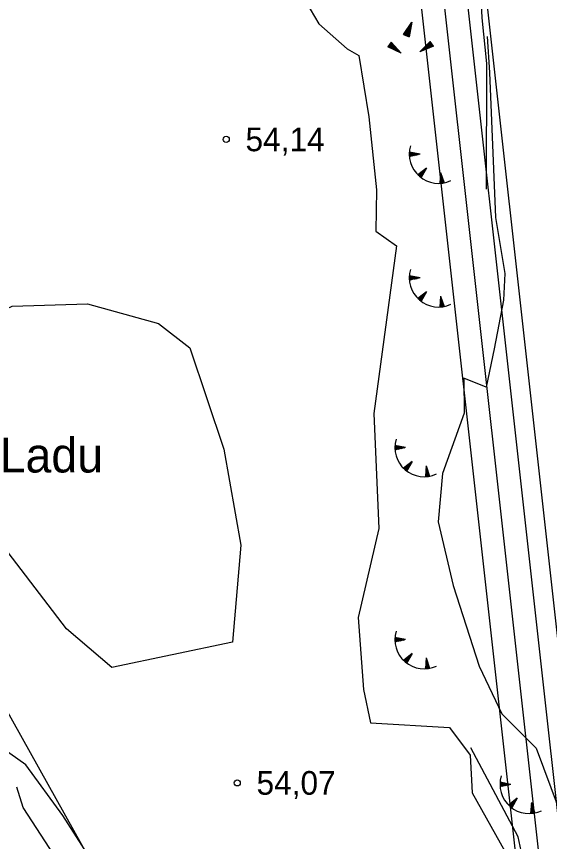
# Model space of a CAD drawing. Extents: x 532503 to 539665, y 6557663 to 6561526.
# Drawn here: x 535432.3 to 535487.5, y 6559649.2 to 6559734.6 of the extents above; entities that cross this region are included whole.
import ezdxf

# ---------------------------------------------------------------- set-up
doc = ezdxf.new("R2010")
doc.units = 0
for name, color, linetype in [('Default', 7, 'Continuous'), ('HALJASTUS', 7, 'Continuous'), ('illumineerimisjooned', 7, 'Continuous'), ('KORGUS-EH2000', 7, 'Continuous'), ('Lõige', 7, 'Continuous'), ('ME_aktiivne', 7, 'Continuous'), ('Plokid', 7, 'Continuous'), ('RELJEEF', 7, 'Continuous')]:
    doc.layers.add(name, color=color, linetype=linetype)

# ---------------------------------------------------------------- blocks, each defined once
blk = doc.blocks.new('POINT_DISPLAY')
at = {"layer": 'Default'}
blk.add_line((0, 0), (0, 0), dxfattribs=at)

msp = doc.modelspace()

# ---------------------------------------------------------------- linework, layer by layer
at = {"layer": 'illumineerimisjooned'}
msp.add_lwpolyline([(535476.016, 6559817.954), (535471.557, 6559803.013), (535503.755, 6559513.648), (535136.963, 6559567.806)], dxfattribs=at)
at = {"layer": 'KORGUS-EH2000'}
for centre in [(535454.026, 6559721.923), (535455.168, 6559655.294)]:
    msp.add_circle(centre, 0.32, dxfattribs=at)
at = {"layer": 'Lõige'}
msp.add_lwpolyline([(535150.705, 6560087.504), (535159.93, 6560069.75), (535218.82, 6559968.7), (535305.655, 6559887.851), (535461.67, 6559608.38), (535506.03, 6559511.29), (535514.367, 6559493.043)], dxfattribs=at)
at = {"layer": 'ME_aktiivne'}
msp.add_lwpolyline([(535181.4, 6559689.09), (535250.12, 6559650.95), (535250.5, 6559651.24), (535480.86, 6559827.19), (535473.59, 6559802.83), (535506.03, 6559511.29), (535131.71, 6559566.56)], close=True, dxfattribs=at)
at = {"layer": 'Plokid'}
for points in [[(535471.605, 6559811.564), (535469.118, 6559803.232), (535501.026, 6559516.477), (535140.335, 6559569.734)], [(535468.361, 6559809.086), (535466.679, 6559803.451), (535498.296, 6559519.306), (535141.263, 6559572.023)]]:
    msp.add_lwpolyline(points, dxfattribs=at)
at = {"layer": 'RELJEEF'}
for p, q in [((535472.407, 6559732.787), (535473.247, 6559734.067)), ((535472.607, 6559733.087), (535473.107, 6559733.297)), ((535472.707, 6559733.237), (535472.957, 6559733.347)), ((535472.807, 6559733.387), (535473.147, 6559733.537)), ((535472.907, 6559733.537), (535473.167, 6559733.657)), ((535472.957, 6559733.347), (535473.127, 6559733.417)), ((535473.247, 6559734.067), (535472.967, 6559732.557)), ((535472.997, 6559733.687), (535473.197, 6559733.767)), ((535473.097, 6559733.837), (535473.217, 6559733.887)), ((535473.197, 6559733.987), (535473.237, 6559734.007)), ((535472.407, 6559732.787), (535473.057, 6559733.067)), ((535472.407, 6559732.787), (535472.967, 6559732.557)), ((535472.507, 6559732.937), (535473.077, 6559733.177)), ((535472.537, 6559732.737), (535473.037, 6559732.947)), ((535472.667, 6559732.677), (535473.017, 6559732.827)), ((535472.807, 6559732.627), (535472.997, 6559732.707)), ((535472.937, 6559732.577), (535472.967, 6559732.587)), ((535471.125, 6559731.985), (535470.755, 6559731.505)), ((535470.775, 6559731.535), (535470.785, 6559731.495)), ((535470.865, 6559731.645), (535470.895, 6559731.445)), ((535470.955, 6559731.765), (535471.005, 6559731.395)), ((535471.035, 6559731.875), (535471.105, 6559731.335)), ((535471.125, 6559731.985), (535472.135, 6559730.845)), ((535471.125, 6559731.985), (535471.215, 6559731.285)), ((535471.245, 6559731.855), (535471.325, 6559731.235)), ((535471.365, 6559731.715), (535471.435, 6559731.185)), ((535471.485, 6559731.585), (535471.515, 6559731.305)), ((535474.083, 6559730.975), (535475.163, 6559732.065)), ((535475.503, 6559731.565), (535474.083, 6559730.975)), ((535475.333, 6559731.495), (535474.723, 6559731.615)), ((535475.503, 6559731.565), (535474.803, 6559731.695)), ((535475.423, 6559731.675), (535474.893, 6559731.785)), ((535475.343, 6559731.795), (535474.973, 6559731.865)), ((535475.263, 6559731.915), (535475.063, 6559731.955)), ((535475.183, 6559732.035), (535475.143, 6559732.035)), ((535475.503, 6559731.565), (535475.163, 6559732.065)), ((535472.135, 6559730.845), (535470.755, 6559731.505)), ((535471.515, 6559731.305), (535471.545, 6559731.125)), ((535471.595, 6559731.445), (535471.655, 6559731.075)), ((535471.715, 6559731.315), (535471.755, 6559731.025)), ((535471.835, 6559731.175), (535471.865, 6559730.975)), ((535471.955, 6559731.045), (535471.975, 6559730.915)), ((535472.075, 6559730.905), (535472.085, 6559730.865)), ((535474.163, 6559731.005), (535474.133, 6559731.015)), ((535474.333, 6559731.075), (535474.213, 6559731.105)), ((535474.503, 6559731.145), (535474.293, 6559731.185)), ((535474.663, 6559731.215), (535474.383, 6559731.275)), ((535474.833, 6559731.285), (535474.463, 6559731.355)), ((535474.733, 6559731.405), (535474.553, 6559731.445)), ((535475.163, 6559731.425), (535474.633, 6559731.525)), ((535475.003, 6559731.355), (535474.733, 6559731.405)), ((535472.993, 6559720.408), (535473.192, 6559720.568)), ((535472.994, 6559720.473), (535473.128, 6559720.58)), ((535472.994, 6559720.345), (535473.257, 6559720.555)), ((535472.995, 6559720.282), (535473.321, 6559720.543)), ((535472.997, 6559720.539), (535473.063, 6559720.593)), ((535472.998, 6559720.22), (535473.386, 6559720.53)), ((535474.114, 6559720.39), (535473.001, 6559720.605)), ((535473.022, 6559720.175), (535473.45, 6559720.518)), ((535473.128, 6559720.196), (535473.514, 6559720.505)), ((535473.234, 6559720.217), (535473.579, 6559720.493)), ((535473.34, 6559720.238), (535473.643, 6559720.48)), ((535473.446, 6559720.259), (535473.708, 6559720.468)), ((535473.552, 6559720.279), (535473.772, 6559720.456)), ((535473.658, 6559720.3), (535473.837, 6559720.443)), ((535473.764, 6559720.321), (535473.901, 6559720.431)), ((535474.114, 6559720.39), (535473.002, 6559720.171)), ((535473.87, 6559720.342), (535473.966, 6559720.418)), ((535473.976, 6559720.363), (535474.03, 6559720.406)), ((535474.778, 6559718.949), (535473.889, 6559718.245)), ((535474.778, 6559718.949), (535474.218, 6559717.964)), ((535474.495, 6559718.452), (535474.505, 6559718.733)), ((535474.548, 6559718.546), (535474.556, 6559718.774)), ((535474.602, 6559718.64), (535474.608, 6559718.815)), ((535474.655, 6559718.733), (535474.659, 6559718.856)), ((535474.708, 6559718.827), (535474.711, 6559718.896)), ((535473.936, 6559718.2), (535473.939, 6559718.285)), ((535473.984, 6559718.155), (535473.99, 6559718.326)), ((535474.033, 6559718.112), (535474.042, 6559718.367)), ((535474.081, 6559718.071), (535474.093, 6559718.407)), ((535474.13, 6559718.031), (535474.145, 6559718.448)), ((535474.179, 6559717.993), (535474.196, 6559718.489)), ((535474.228, 6559717.982), (535474.248, 6559718.53)), ((535474.282, 6559718.076), (535474.299, 6559718.57)), ((535474.335, 6559718.17), (535474.351, 6559718.611)), ((535474.388, 6559718.264), (535474.402, 6559718.652)), ((535474.442, 6559718.358), (535474.454, 6559718.693)), ((535476.242, 6559718.501), (535476.157, 6559717.371)), ((535476.548, 6559717.545), (535476.196, 6559717.893)), ((535476.515, 6559717.648), (535476.201, 6559717.958)), ((535476.482, 6559717.75), (535476.206, 6559718.024)), ((535476.449, 6559717.853), (535476.211, 6559718.089)), ((535476.417, 6559717.956), (535476.216, 6559718.154)), ((535476.384, 6559718.059), (535476.221, 6559718.22)), ((535476.351, 6559718.162), (535476.226, 6559718.285)), ((535476.318, 6559718.265), (535476.231, 6559718.351)), ((535476.285, 6559718.368), (535476.236, 6559718.416)), ((535476.242, 6559718.501), (535476.588, 6559717.422)), ((535476.223, 6559717.374), (535476.162, 6559717.434)), ((535476.289, 6559717.38), (535476.167, 6559717.5)), ((535476.353, 6559717.386), (535476.172, 6559717.565)), ((535476.416, 6559717.394), (535476.177, 6559717.631)), ((535476.478, 6559717.403), (535476.182, 6559717.696)), ((535476.539, 6559717.413), (535476.187, 6559717.762)), ((535476.581, 6559717.442), (535476.192, 6559717.827)), ((535472.993, 6559707.604), (535473.192, 6559707.763)), ((535472.994, 6559707.669), (535473.128, 6559707.776)), ((535472.994, 6559707.54), (535473.257, 6559707.751)), ((535472.995, 6559707.477), (535473.321, 6559707.738)), ((535472.997, 6559707.735), (535473.063, 6559707.788)), ((535472.998, 6559707.416), (535473.386, 6559707.726)), ((535474.114, 6559707.585), (535473.001, 6559707.8)), ((535473.022, 6559707.371), (535473.45, 6559707.713)), ((535473.128, 6559707.392), (535473.514, 6559707.701)), ((535473.234, 6559707.412), (535473.579, 6559707.688)), ((535473.34, 6559707.433), (535473.643, 6559707.676)), ((535473.446, 6559707.454), (535473.708, 6559707.664)), ((535473.552, 6559707.475), (535473.772, 6559707.651)), ((535473.658, 6559707.496), (535473.837, 6559707.639)), ((535473.764, 6559707.517), (535473.901, 6559707.626)), ((535473.87, 6559707.537), (535473.966, 6559707.614)), ((535474.114, 6559707.585), (535473.002, 6559707.367)), ((535473.976, 6559707.558), (535474.03, 6559707.601)), ((535474.778, 6559706.145), (535473.889, 6559705.441)), ((535474.778, 6559706.145), (535474.218, 6559705.159)), ((535474.495, 6559705.647), (535474.505, 6559705.929)), ((535474.548, 6559705.741), (535474.556, 6559705.97)), ((535474.602, 6559705.835), (535474.608, 6559706.01)), ((535474.655, 6559705.929), (535474.659, 6559706.051)), ((535474.708, 6559706.023), (535474.711, 6559706.092)), ((535473.936, 6559705.395), (535473.939, 6559705.48)), ((535473.984, 6559705.35), (535473.99, 6559705.521)), ((535474.033, 6559705.307), (535474.042, 6559705.562)), ((535474.081, 6559705.266), (535474.093, 6559705.603)), ((535474.13, 6559705.227), (535474.145, 6559705.644)), ((535474.179, 6559705.189), (535474.196, 6559705.684)), ((535474.228, 6559705.177), (535474.248, 6559705.725)), ((535474.282, 6559705.271), (535474.299, 6559705.766)), ((535474.335, 6559705.365), (535474.351, 6559705.807)), ((535474.388, 6559705.459), (535474.402, 6559705.847)), ((535474.442, 6559705.553), (535474.454, 6559705.888)), ((535476.242, 6559705.697), (535476.157, 6559704.566)), ((535476.548, 6559704.74), (535476.196, 6559705.088)), ((535476.515, 6559704.843), (535476.201, 6559705.154)), ((535476.482, 6559704.946), (535476.206, 6559705.219)), ((535476.449, 6559705.049), (535476.211, 6559705.284)), ((535476.417, 6559705.152), (535476.216, 6559705.35)), ((535476.384, 6559705.255), (535476.221, 6559705.415)), ((535476.351, 6559705.358), (535476.226, 6559705.481)), ((535476.318, 6559705.46), (535476.231, 6559705.546)), ((535476.285, 6559705.563), (535476.236, 6559705.612)), ((535476.242, 6559705.697), (535476.588, 6559704.617)), ((535476.223, 6559704.57), (535476.162, 6559704.63)), ((535476.289, 6559704.575), (535476.167, 6559704.695)), ((535476.353, 6559704.582), (535476.172, 6559704.761)), ((535476.416, 6559704.589), (535476.177, 6559704.826)), ((535476.478, 6559704.598), (535476.182, 6559704.892)), ((535476.539, 6559704.608), (535476.187, 6559704.957)), ((535476.581, 6559704.637), (535476.192, 6559705.023)), ((535471.496, 6559690.097), (535471.63, 6559690.203)), ((535471.496, 6559690.032), (535471.694, 6559690.191)), ((535471.496, 6559689.968), (535471.759, 6559690.179)), ((535471.498, 6559689.905), (535471.823, 6559690.166)), ((535471.499, 6559690.163), (535471.565, 6559690.216)), ((535471.501, 6559689.844), (535471.888, 6559690.154)), ((535472.616, 6559690.013), (535471.503, 6559690.228)), ((535472.616, 6559690.013), (535471.504, 6559689.795)), ((535471.524, 6559689.799), (535471.952, 6559690.141)), ((535471.63, 6559689.819), (535472.017, 6559690.129)), ((535471.736, 6559689.84), (535472.081, 6559690.116)), ((535471.842, 6559689.861), (535472.146, 6559690.104)), ((535471.948, 6559689.882), (535472.21, 6559690.091)), ((535472.054, 6559689.903), (535472.275, 6559690.079)), ((535472.16, 6559689.924), (535472.339, 6559690.066)), ((535472.266, 6559689.944), (535472.403, 6559690.054)), ((535472.372, 6559689.965), (535472.468, 6559690.042)), ((535472.478, 6559689.986), (535472.532, 6559690.029)), ((535473.28, 6559688.573), (535472.391, 6559687.869)), ((535472.535, 6559687.735), (535472.544, 6559687.99)), ((535472.584, 6559687.694), (535472.595, 6559688.031)), ((535472.632, 6559687.654), (535472.647, 6559688.071)), ((535472.681, 6559687.616), (535472.698, 6559688.112)), ((535473.28, 6559688.573), (535472.72, 6559687.587)), ((535472.731, 6559687.605), (535472.75, 6559688.153)), ((535472.784, 6559687.699), (535472.801, 6559688.194)), ((535472.837, 6559687.793), (535472.853, 6559688.234)), ((535472.891, 6559687.887), (535472.904, 6559688.275)), ((535472.944, 6559687.981), (535472.956, 6559688.316)), ((535472.997, 6559688.075), (535473.007, 6559688.357)), ((535473.051, 6559688.169), (535473.059, 6559688.397)), ((535473.104, 6559688.263), (535473.11, 6559688.438)), ((535473.157, 6559688.357), (535473.162, 6559688.479)), ((535473.211, 6559688.451), (535473.213, 6559688.52)), ((535474.744, 6559688.125), (535474.66, 6559686.994)), ((535474.82, 6559687.888), (535474.733, 6559687.974)), ((535474.787, 6559687.991), (535474.738, 6559688.04)), ((535474.744, 6559688.125), (535475.09, 6559687.045)), ((535472.438, 6559687.823), (535472.441, 6559687.908)), ((535472.487, 6559687.778), (535472.493, 6559687.949)), ((535474.791, 6559687.003), (535474.669, 6559687.123)), ((535474.855, 6559687.009), (535474.674, 6559687.189)), ((535474.918, 6559687.017), (535474.679, 6559687.254)), ((535474.981, 6559687.026), (535474.684, 6559687.32)), ((535475.042, 6559687.036), (535474.689, 6559687.385)), ((535475.083, 6559687.065), (535474.694, 6559687.45)), ((535475.05, 6559687.168), (535474.699, 6559687.516)), ((535475.018, 6559687.271), (535474.704, 6559687.581)), ((535474.985, 6559687.374), (535474.708, 6559687.647)), ((535474.952, 6559687.477), (535474.713, 6559687.712)), ((535474.919, 6559687.58), (535474.718, 6559687.778)), ((535474.886, 6559687.682), (535474.723, 6559687.843)), ((535474.853, 6559687.785), (535474.728, 6559687.909)), ((535474.725, 6559686.998), (535474.664, 6559687.058)), ((535471.496, 6559670.209), (535471.63, 6559670.316)), ((535471.496, 6559670.144), (535471.694, 6559670.303)), ((535471.496, 6559670.08), (535471.759, 6559670.291)), ((535471.498, 6559670.017), (535471.823, 6559670.278)), ((535471.499, 6559670.275), (535471.565, 6559670.328)), ((535471.501, 6559669.956), (535471.888, 6559670.266)), ((535472.616, 6559670.125), (535471.503, 6559670.34)), ((535472.616, 6559670.125), (535471.504, 6559669.907)), ((535471.524, 6559669.911), (535471.952, 6559670.253)), ((535471.63, 6559669.932), (535472.017, 6559670.241)), ((535471.736, 6559669.952), (535472.081, 6559670.228)), ((535471.842, 6559669.973), (535472.146, 6559670.216)), ((535471.948, 6559669.994), (535472.21, 6559670.203)), ((535472.054, 6559670.015), (535472.275, 6559670.191)), ((535472.16, 6559670.036), (535472.339, 6559670.179)), ((535472.266, 6559670.056), (535472.403, 6559670.166)), ((535472.372, 6559670.077), (535472.468, 6559670.154)), ((535472.478, 6559670.098), (535472.532, 6559670.141)), ((535473.28, 6559668.685), (535472.391, 6559667.981)), ((535473.28, 6559668.685), (535472.72, 6559667.699)), ((535472.837, 6559667.905), (535472.853, 6559668.347)), ((535472.891, 6559667.999), (535472.904, 6559668.387)), ((535472.944, 6559668.093), (535472.956, 6559668.428)), ((535472.997, 6559668.187), (535473.007, 6559668.469)), ((535473.051, 6559668.281), (535473.059, 6559668.51)), ((535473.104, 6559668.375), (535473.11, 6559668.55)), ((535473.157, 6559668.469), (535473.162, 6559668.591)), ((535473.211, 6559668.563), (535473.213, 6559668.632)), ((535472.438, 6559667.935), (535472.441, 6559668.02)), ((535472.487, 6559667.89), (535472.493, 6559668.061)), ((535472.535, 6559667.847), (535472.544, 6559668.102)), ((535472.584, 6559667.806), (535472.595, 6559668.143)), ((535472.632, 6559667.767), (535472.647, 6559668.183)), ((535472.681, 6559667.729), (535472.698, 6559668.224)), ((535472.731, 6559667.717), (535472.75, 6559668.265)), ((535472.784, 6559667.811), (535472.801, 6559668.306)), ((535474.744, 6559668.237), (535474.66, 6559667.106)), ((535475.042, 6559667.148), (535474.689, 6559667.497)), ((535475.083, 6559667.177), (535474.694, 6559667.563)), ((535475.05, 6559667.28), (535474.699, 6559667.628)), ((535475.018, 6559667.383), (535474.704, 6559667.694)), ((535474.985, 6559667.486), (535474.708, 6559667.759)), ((535474.952, 6559667.589), (535474.713, 6559667.824)), ((535474.919, 6559667.692), (535474.718, 6559667.89)), ((535474.886, 6559667.795), (535474.723, 6559667.955)), ((535474.853, 6559667.897), (535474.728, 6559668.021)), ((535474.82, 6559668), (535474.733, 6559668.086)), ((535474.787, 6559668.103), (535474.738, 6559668.152)), ((535474.744, 6559668.237), (535475.09, 6559667.157)), ((535474.725, 6559667.11), (535474.664, 6559667.17)), ((535474.791, 6559667.115), (535474.669, 6559667.235)), ((535474.855, 6559667.122), (535474.674, 6559667.301)), ((535474.918, 6559667.129), (535474.679, 6559667.366)), ((535474.981, 6559667.138), (535474.684, 6559667.432)), ((535482.389, 6559655.16), (535482.588, 6559655.319)), ((535482.389, 6559655.096), (535482.652, 6559655.307)), ((535482.39, 6559655.225), (535482.523, 6559655.332)), ((535482.391, 6559655.033), (535482.716, 6559655.294)), ((535482.392, 6559655.291), (535482.459, 6559655.344)), ((535482.394, 6559654.972), (535482.781, 6559655.282)), ((535483.509, 6559655.141), (535482.396, 6559655.356)), ((535483.509, 6559655.141), (535482.397, 6559654.923)), ((535482.418, 6559654.927), (535482.845, 6559655.269)), ((535482.524, 6559654.948), (535482.91, 6559655.257)), ((535482.63, 6559654.968), (535482.974, 6559655.244)), ((535482.736, 6559654.989), (535483.039, 6559655.232)), ((535482.842, 6559655.01), (535483.103, 6559655.219)), ((535482.948, 6559655.031), (535483.168, 6559655.207)), ((535483.054, 6559655.052), (535483.232, 6559655.195)), ((535483.16, 6559655.072), (535483.297, 6559655.182)), ((535483.266, 6559655.093), (535483.361, 6559655.17)), ((535483.372, 6559655.114), (535483.426, 6559655.157)), ((535484.173, 6559653.701), (535483.284, 6559652.997)), ((535483.331, 6559652.951), (535483.334, 6559653.036)), ((535483.38, 6559652.906), (535483.386, 6559653.077)), ((535483.428, 6559652.863), (535483.437, 6559653.118)), ((535483.477, 6559652.822), (535483.489, 6559653.159)), ((535483.525, 6559652.783), (535483.54, 6559653.199)), ((535483.574, 6559652.745), (535483.592, 6559653.24)), ((535484.173, 6559653.701), (535483.613, 6559652.715)), ((535483.624, 6559652.733), (535483.643, 6559653.281)), ((535483.677, 6559652.827), (535483.695, 6559653.322)), ((535483.73, 6559652.921), (535483.746, 6559653.363)), ((535483.784, 6559653.015), (535483.797, 6559653.403)), ((535483.837, 6559653.109), (535483.849, 6559653.444)), ((535483.89, 6559653.203), (535483.9, 6559653.485)), ((535483.944, 6559653.297), (535483.952, 6559653.526)), ((535483.997, 6559653.391), (535484.003, 6559653.566)), ((535484.05, 6559653.485), (535484.055, 6559653.607)), ((535484.104, 6559653.579), (535484.106, 6559653.648)), ((535485.637, 6559653.253), (535485.553, 6559652.122)), ((535485.779, 6559652.811), (535485.616, 6559652.971)), ((535485.746, 6559652.913), (535485.621, 6559653.037)), ((535485.713, 6559653.016), (535485.626, 6559653.102)), ((535485.68, 6559653.119), (535485.631, 6559653.168)), ((535485.637, 6559653.253), (535485.983, 6559652.173)), ((535485.618, 6559652.126), (535485.557, 6559652.186)), ((535485.684, 6559652.131), (535485.562, 6559652.251)), ((535485.748, 6559652.138), (535485.567, 6559652.317)), ((535485.812, 6559652.145), (535485.572, 6559652.382)), ((535485.874, 6559652.154), (535485.577, 6559652.448)), ((535485.935, 6559652.164), (535485.582, 6559652.513)), ((535485.977, 6559652.193), (535485.587, 6559652.579)), ((535485.944, 6559652.296), (535485.592, 6559652.644)), ((535485.911, 6559652.399), (535485.597, 6559652.71)), ((535485.878, 6559652.502), (535485.602, 6559652.775)), ((535485.845, 6559652.605), (535485.607, 6559652.84)), ((535485.812, 6559652.708), (535485.611, 6559652.906))]:
    msp.add_line(p, q, dxfattribs=at)
for points in [[(535478.755, 6559773.191), (535480.505, 6559734.519), (535481.004, 6559729.777), (535480.971, 6559716.757)], [(535461.821, 6559736.957), (535463.615, 6559733.884), (535466.565, 6559731.305), (535467.764, 6559730.613), (535468.815, 6559724.271), (535469.594, 6559716.704), (535469.533, 6559712.409), (535471.681, 6559710.891), (535469.317, 6559693.551), (535469.833, 6559681.643), (535467.694, 6559672.404), (535468.255, 6559664.972), (535468.961, 6559661.499), (535477.154, 6559661.037), (535479.299, 6559658.175), (535479.511, 6559654.274), (535483.376, 6559647.365)], [(535461.821, 6559736.957), (535463.615, 6559733.884), (535466.565, 6559731.305), (535467.764, 6559730.613), (535468.815, 6559724.271), (535469.594, 6559716.704), (535469.533, 6559712.409), (535471.681, 6559710.891), (535469.317, 6559693.551), (535469.833, 6559681.643), (535467.694, 6559672.404), (535468.255, 6559664.972), (535468.961, 6559661.499), (535477.154, 6559661.037), (535479.299, 6559658.175), (535479.511, 6559654.274), (535483.376, 6559647.365)], [(535461.821, 6559736.957), (535463.615, 6559733.884), (535466.565, 6559731.305), (535467.764, 6559730.613), (535468.815, 6559724.271), (535469.594, 6559716.704), (535469.533, 6559712.409), (535471.681, 6559710.891), (535469.317, 6559693.551), (535469.833, 6559681.643), (535467.694, 6559672.404), (535468.255, 6559664.972), (535468.961, 6559661.499), (535477.154, 6559661.037), (535479.299, 6559658.175), (535479.511, 6559654.274), (535483.376, 6559647.365)], [(535465.729, 6559608.774), (535462.127, 6559614.941), (535454.362, 6559625.606), (535449.537, 6559632.516), (535437.1, 6559651.905), (535433.274, 6559657.174), (535429.675, 6559659.673), (535422.288, 6559654.665), (535420.529, 6559653.22), (535418.073, 6559654.093), (535416.095, 6559657.722), (535409.073, 6559665.547), (535406.836, 6559668.456), (535387.775, 6559691.478), (535381.964, 6559699.759), (535374.616, 6559708.105), (535371.861, 6559711.931), (535367.481, 6559717.176), (535364.865, 6559720.505), (535361.879, 6559724.065), (535359.666, 6559725.917), (535366.933, 6559734.437)], [(535481.05, 6559732.569), (535481.311, 6559728.852), (535481.907, 6559713.82)], [(535481.907, 6559713.82), (535482.887, 6559708.035), (535482.755, 6559705.284), (535481.77, 6559700.246), (535480.97, 6559696.252), (535478.642, 6559697.195), (535478.669, 6559693.568), (535476.445, 6559687.342), (535475.974, 6559682.338), (535477.546, 6559675.724), (535480.239, 6559667.38), (535482.586, 6559662.438), (535486.136, 6559658.905)], [(535442.192, 6559667.23), (535437.471, 6559671.239), (535429.518, 6559681.634), (535423.397, 6559690.08), (535421.862, 6559696.251), (535422.861, 6559699.416), (535425.535, 6559701.726), (535431.855, 6559704.653), (535439.658, 6559704.885), (535447.003, 6559702.867), (535450.275, 6559700.354), (535453.786, 6559689.835), (535455.531, 6559679.895), (535454.687, 6559669.862), (535442.192, 6559667.23)], [(535492.143, 6559591.588), (535491.563, 6559598.215), (535489.928, 6559604.651), (535489.777, 6559609.84), (535489.802, 6559614), (535490.547, 6559619.484), (535490.161, 6559620.629), (535488.201, 6559623.458), (535486.394, 6559627.7), (535485.358, 6559630.898), (535485.506, 6559634.665), (535486.66, 6559639.564), (535485.092, 6559645.859), (535484.267, 6559649.726), (535479.362, 6559658.935)], [(535486.136, 6559658.905), (535488.416, 6559652.798), (535489.591, 6559649.203), (535490.44, 6559638.722), (535491.996, 6559627.624), (535492.287, 6559623.413), (535492.105, 6559617.099), (535491.774, 6559609.247), (535491.363, 6559604.035), (535492.222, 6559601.161), (535492.653, 6559594.053), (535492.143, 6559591.588)], [(535468.855, 6559595.061), (535464.157, 6559599.828), (535461.947, 6559605.714), (535461.342, 6559609.346), (535457.864, 6559616.081), (535453.814, 6559620.81), (535449.904, 6559626.129), (535442.966, 6559639.007), (535437.118, 6559646.423), (535432.987, 6559652.756), (535432.336, 6559654.838)]]:
    msp.add_lwpolyline(points, dxfattribs=at)
for centre in [(535476.02, 6559720.395), (535476.02, 6559707.59), (535474.523, 6559690.018), (535474.523, 6559670.13), (535485.416, 6559655.146)]:
    msp.add_arc(centre, 3.027, 163.42341, 295.17451, dxfattribs=at)

# ---------------------------------------------------------------- block references
at = {"layer": 'RELJEEF', "xscale": 100, "yscale": 100}
for p in [(535472.407, 6559732.787), (535471.125, 6559731.985), (535475.503, 6559731.565)]:
    msp.add_blockref('POINT_DISPLAY', p, dxfattribs=at)

# ---------------------------------------------------------------- texts
at = {"layer": 'HALJASTUS'}
msp.add_text('Ladu', height=3.6, dxfattribs=at).set_placement((535430.564, 6559687.434))
at = {"layer": 'KORGUS-EH2000'}
for s, p in [('54,14 ', (535456.026, 6559720.698)), ('54,07 ', (535457.168, 6559654.069))]:
    msp.add_text(s, height=2.45, dxfattribs=at).set_placement(p)

doc.saveas('drawing.dxf')
